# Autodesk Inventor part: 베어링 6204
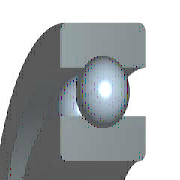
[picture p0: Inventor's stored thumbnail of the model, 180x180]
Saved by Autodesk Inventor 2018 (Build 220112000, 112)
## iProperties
IsCustomPart: 0
Created: 2018-09
Part Number: 베어링 6204
Material: 스테인리스강
Description: 깊은 그루브 볼 베어링
Document SubType Name: Modeling
Standard: KS B 2023
Standards Organization: KS
Language: ko-KR
Size Designation: 6204 - 20 x 47 x 14
Categories: <MemberInstance><Categories><Category DisplayName="샤프트 부품" InternalName="7f7aeb1f-a693-4053-b835-cee3144e0d98" Mnemonic="SHFT"><Category DisplayName="베어링" Inter
Density: 8.08 g/cm^3
Mass: 107.173 g
Surface Area: 87.8912 cm^2
Volume: 13.264 cm^3
Appearance: 노란색
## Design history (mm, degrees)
sketch "스케치" dims "d0" = 7.02 (= -0.26 x WD + 0.26 x BD)
  geometry: L1 (3.49, 16.75)-(10.51, 16.75); L2 (7, 16.75)-(7, 13.24); L3 (7, 16.75)-(7, 20.26); L4 (4.392, 14.401)-(0, 14.401); L5 (0, 10)-(14, 10); L6 (4.392, 19.099)-(0, 19.099); L7 (0, 23.5)-(14, 23.5); L8 (14, 10)-(14, 14.401); L9 (9.608, 14.401)-(14, 14.401); L10 (9.608, 19.099)-(14, 19.099); L11 (14, 23.5)-(14, 19.099); L12 (-1.4, 0)-(8.4, 0) reference; L13 (0, -0.3)-(0, 5.3) reference
  constraints: 22 end point, 4 point on line, 2 collinear, 2 perpendicular, 2 symmetric about line, 1 midpoint, 1 parallel, 14 other
  dimensions: "d9" = 20 diameter of L5 L12 (= WD); "d11" = 47 diameter of L7 L12 (= BD); "d12" = 14 distance between parallel lines of L8 L13 (= KB); "d13" = 28.802 diameter of L9 L12 (= 0.326 x BD + 0.674 x WD)
revolve "본체" stored, may be unused: angle "d6" = 90 deg
revolve "볼" stored, may be unused: angle "d7" = 90 deg
pattern_circular "IDS_ARRAYBALL[SIMPL:T]" dims angle "d3" = 360 deg
body "Solid1"
fillet "모깎기1" dims "d1" = 1 (= KRS)
other parameters: "WD" = 20 [user parameter; used in 5 equation terms], "BD" = 47 [user parameter; used in 5 equation terms], "KB" = 14 [user parameter; used in 1 equation term], "KRS" = 1 [user parameter; used in 1 equation term], "d4" = 0, "d5" = 0, "d8" = 0, "d14" = 0, "d15" = 0, "BBA" = 0 [user parameter], "BC0" = 6550000 [user parameter], "BC" = 1.27e+07 [user parameter], "BR" = 23.5 (= 0.5 x BD) [user parameter]
